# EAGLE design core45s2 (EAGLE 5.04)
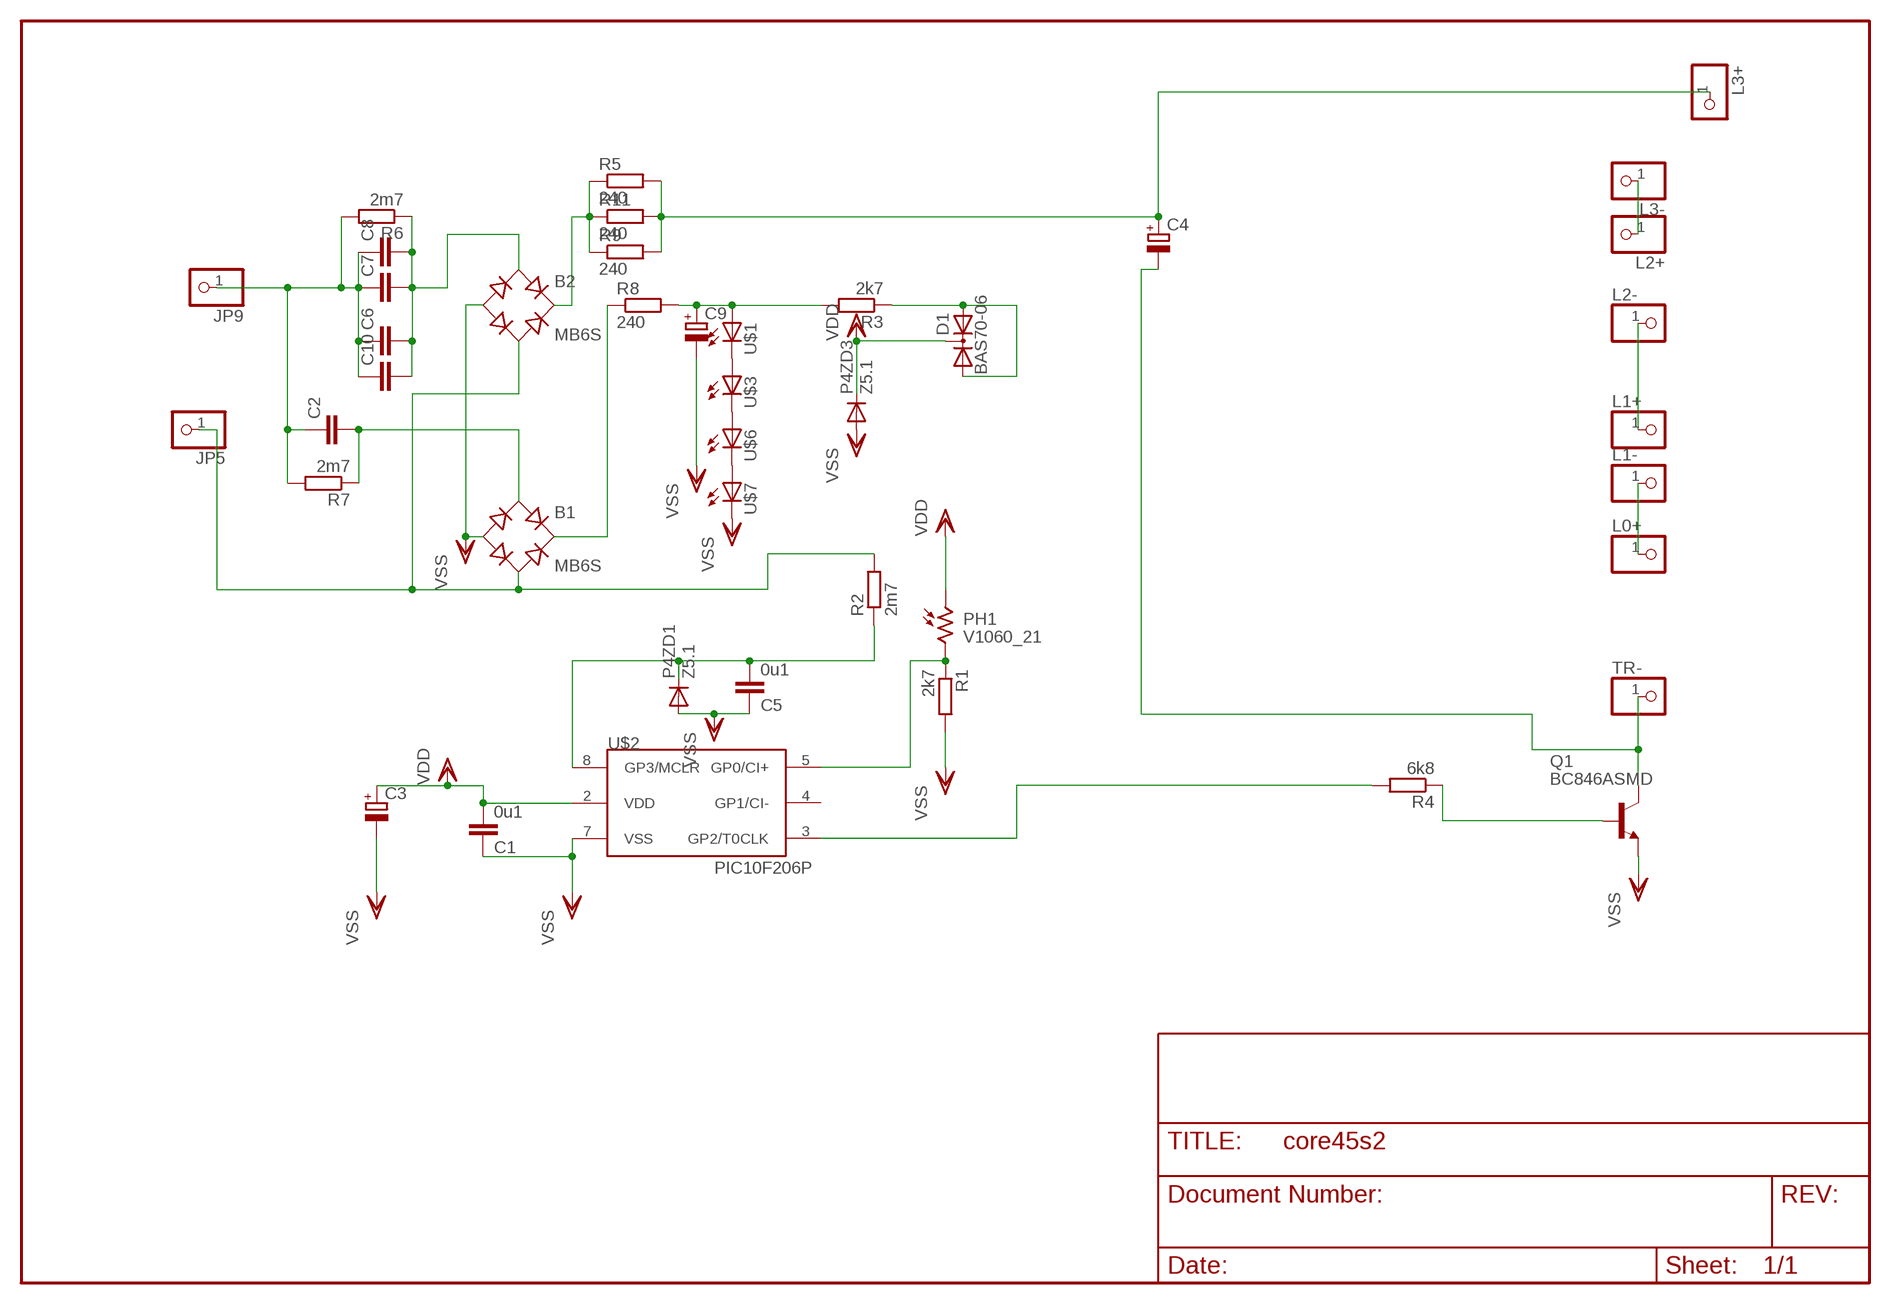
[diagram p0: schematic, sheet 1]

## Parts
B1  MB6S  [SOIC-4]
B2  MB6S  [SOIC-4]
C1  0u1  C-EUC1206  [C1206]
C2  C-EU102-043X133  [C102-043X133]
C3  CPOL-EU5-13  [2,5-5-FLAT]
C4  CPOL-EUTT5D11L  [TT5D11L]
C5  0u1  C-EUC1206  [C1206]
C6  C-EU150-064X183  [C150-064X183]
C7  C-EU150-054X183  [C150-054X183]
C8  C-EU150-054X183  [C150-054X183]
C9  CPOL-EUTT5D11L  [TT5D11L]
C10  C-EU150-064X183  [C150-064X183]
D1  BAS70-06  [SOT23]
JP5  PINHD-1X1  [1X01]
JP9  PINHD-1X1  [1X01]
L0+  PINHD-1X1  [1X01]
L1+  PINHD-1X1  [1X01]
L1-  PINHD-1X1  [1X01]
L2+  PINHD-1X1  [1X01]
L2-  PINHD-1X1  [1X01]
L3+  PINHD-1X1  [1X01]
L3-  PINHD-1X1  [1X01]
P4ZD1  Z5.1  DIODE-MINIMELF  [MINIMELF]
P4ZD3  Z5.1  DIODE-MINIMELF  [MINIMELF]
PH1  V1060_21  [TO-5_V10]
Q1  BC846ASMD  [SOT23]
R1  2k7  R-EU_R0805  [R0805]
R2  2m7  R-EU_R1206  [R1206]
R3  2k7  R-EU_R0805  [R0805]
R4  6k8  R-EU_R0805  [R0805]
R5  240  R-EU_0204/2V  [0204V]
R6  2m7  R-EU_R1206  [R1206]
R7  2m7  R-EU_R1206  [R1206]
R8  240  R-EU_0204/5  [0204/5]
R9  240  R-EU_0204/5  [0204/5]
R11  240  R-EU_0204/5  [0204/5]
TR-  PINHD-1X1  [1X01]
U$1  LED5MM  [LED5MM]
U$2  PIC10F206P  [DIL8]
U$3  LED5MM  [LED5MM]
U$6  LED5MM  [LED5MM]
U$7  LED5MM  [LED5MM]

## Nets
AC1: B1.~2(AC2) B2.~2(AC2) JP5.1 R2.2
AC2: C2.1 C6.1 C7.1 C8.1 C10.1 JP9.1 R6.2 R7.2
D+: C4.+ L3+.1 R5.2 R9.2 R11.2
LED-: C4.- Q1.3(C) TR-.1
N$1: C5.2 P4ZD1.C R2.1 U$2.8(GP3/MCLR)
N$2: B1.+ R8.1
N$3: L0+.1 L1-.1
N$4: C9.+ R3.2 R8.2 U$1.A
N$5: D1.1(A1) D1.2(A2) R3.1
N$6: L1+.1 L2-.1
N$7: U$1.K(C) U$3.A
N$8: B1.~1(AC1) C2.2 R7.1
N$9: B2.~1(AC1) C6.2 C7.2 C8.2 C10.2 R6.1
N$10: U$3.K(C) U$6.A
N$11: B2.+ R5.1 R9.1 R11.1
N$12: Q1.1(B) R4.1
N$13: L2+.1 L3-.1
N$15: R4.2 U$2.3(GP2/T0CLK)
N$16: U$6.K(C) U$7.A
N$17: PH1.2 R1.1 U$2.5(GP0/CI+)
VDD: C1.2 C3.+ D1.3(C) P4ZD3.C PH1.1 U$2.2(VDD)
VSS: B1.- B2.- C1.1 C3.- C5.1 C9.- P4ZD1.A P4ZD3.A Q1.2(E) R1.2 U$2.7(VSS) U$7.K(C)
Unconnected: U$2.4(GP1/CI-)

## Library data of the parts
B1 B2 = rectifier:MB*S: Bridge Rectifier Source: http://www.fairchildsemi.com/ds/MB/MB6S.pdf
C1 C5 = rcl:C-EU: CAPACITOR, European symbol
C2 C6-C8 C10 = rcl-2:C-EU: CAPACITOR, European symbol
C3 C4 C9 = rcl-2:CPOL-EU: POLARIZED CAPACITOR, European symbol
D1 = diode:BAS70-06: Silicon Schottky Diodes General-purpose diode for high-speed switching
JP5 JP9 L0+ L1+ L1- L2+ L2- L3+ L3- TR- = pinhead(2):PINHD-1X1: PIN HEADER
P4ZD1 P4ZD3 = diode:DIODE-: DIODE
PH1 = photo-elements:?1060*: Sensor Street Light control
Q1 = transistor-npn:BC846*: NPN Transistor
R1-R9 R11 = rcl-2:R-EU_: RESISTOR, European symbol
U$1 U$3 U$6 U$7 = led(3):LED: LED
U$2 = microchip-3:PIC10F2*: uPC nW 0,25/0,5k Program Flash memory Comparator

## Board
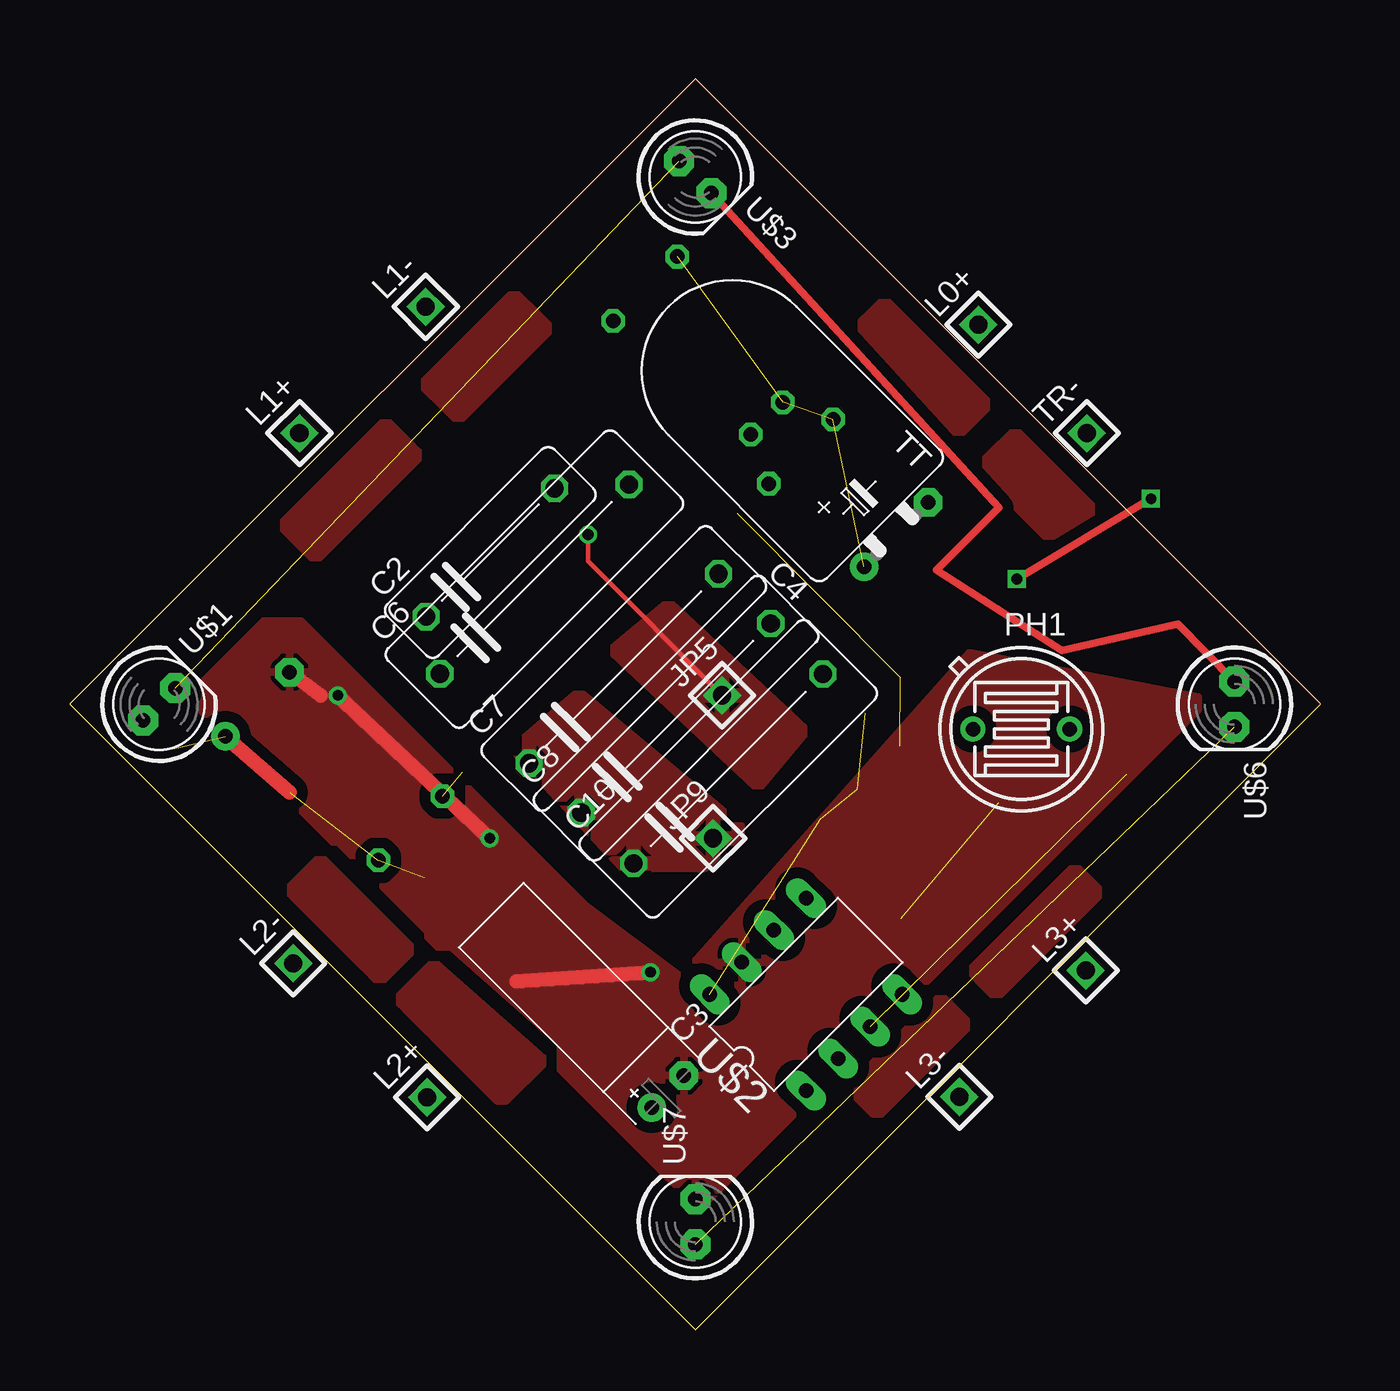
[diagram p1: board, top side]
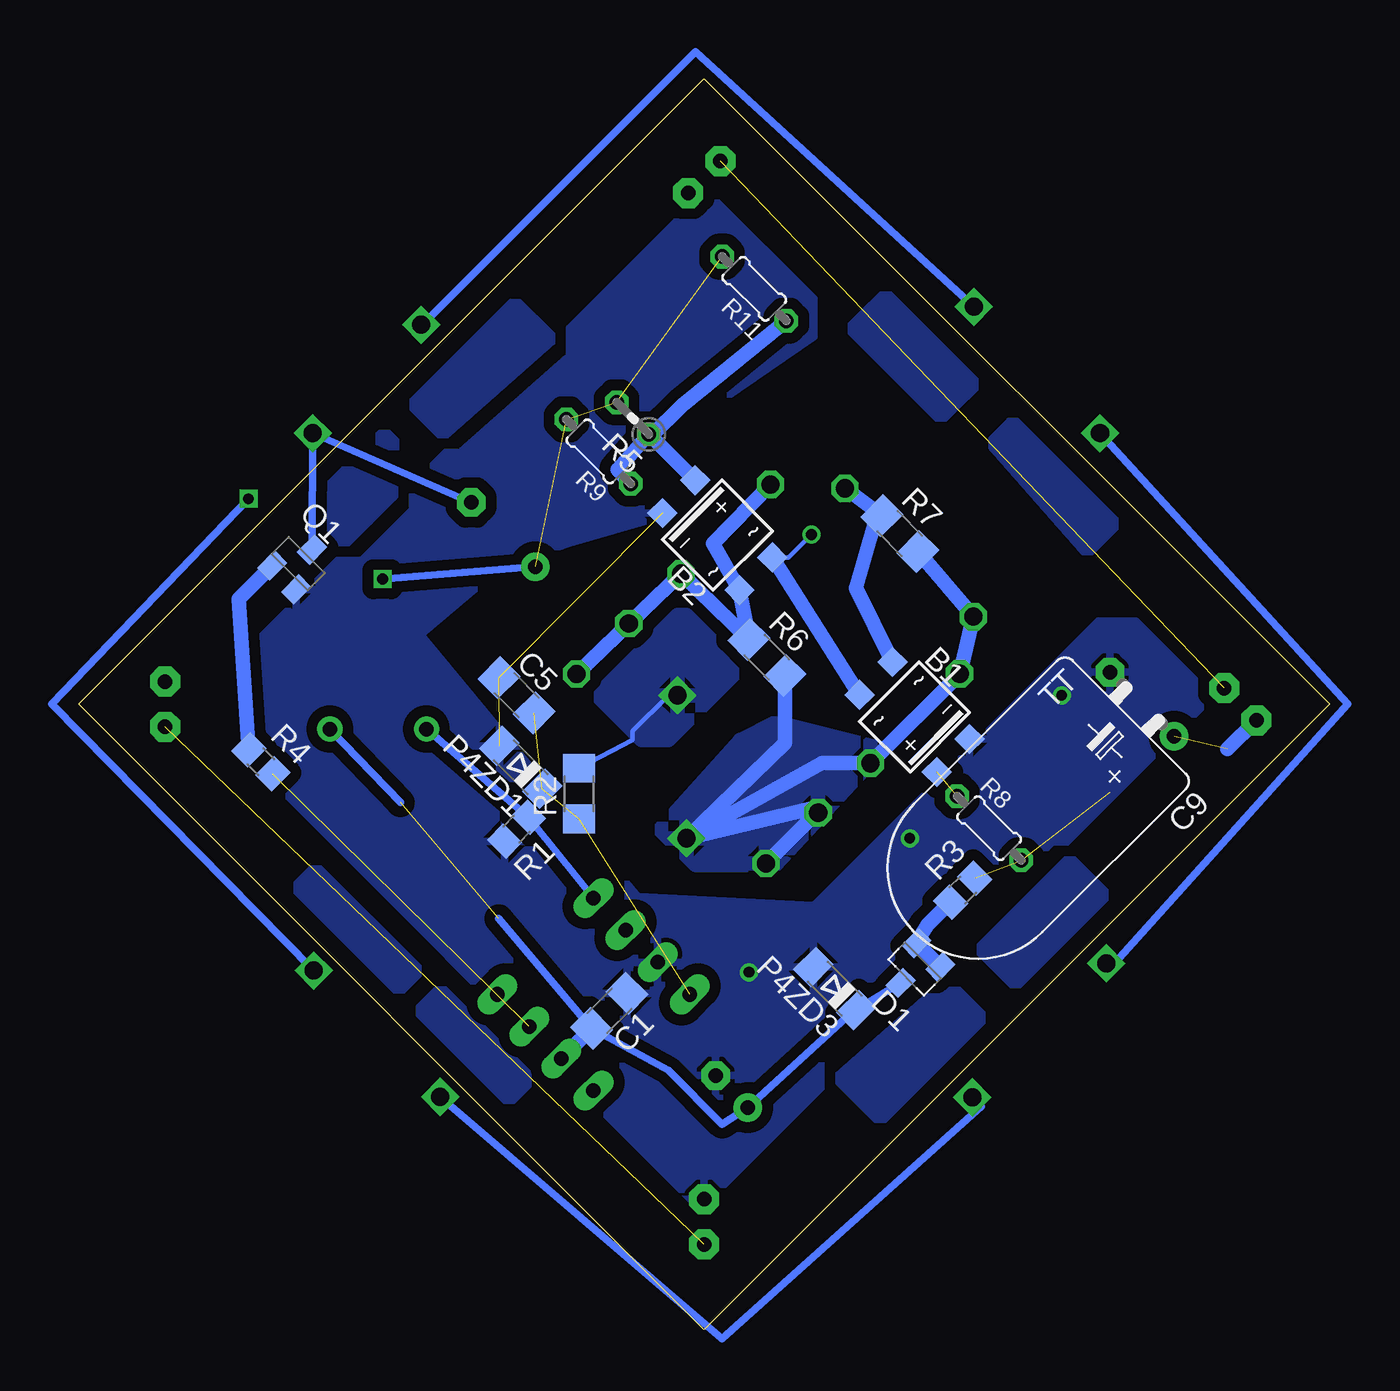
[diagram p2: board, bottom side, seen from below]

Size 70 x 70 mm. Coordinates in mm from the lower left corner, seen from the top.
Outline: 35,0 70,35 35,70 0,35 35,0
Copper layers (1*16): Top 0.035mm / dielectric 1.5mm / Bottom 0.035mm
Design rules "default": minimum track width 10mil, minimum drill 24mil, track to track 8mil, track to pad 8mil, pad to pad 8mil, via to via 8mil, smd to smd 8mil, copper to edge 40mil, drill to drill 8mil, minimum pad ring 10mil, minimum via ring 8mil, stop-mask expansion 4mil, vias tented up to drill 0mil, thermal gap 10mil

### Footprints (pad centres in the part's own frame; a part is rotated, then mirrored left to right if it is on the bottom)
SOIC-4 = smd 1.2 x 1.2: + 1.3,3.05; - -1.3,3.05; ~1 -1.3,-3.05; ~2 1.3,-3.05
C1206 = smd 1.6 x 1.8: 1 -1.4,0; 2 1.4,0
C102-043X133 = drill 1.016 octagon: 1 -5.08,0; 2 5.08,0
2,5-5-FLAT = drill 0.813 pad 1.6 round: + -1.27,0 | drill 0.813 pad 1.6 octagon: - 1.27,0
TT5D11L = drill 0.813 pad 1.6 round: + -2.54,0 | drill 0.813 pad 1.6 octagon: - 2.54,0
C150-064X183 = drill 1.016 octagon: 1 -7.493,0; 2 7.493,0
C150-054X183 = drill 1.016 octagon: 1 -7.493,0; 2 7.493,0
SOT23 = smd 1 x 1.4: 1 -0.95,-1.1; 2 0.95,-1.1; 3 0,1.1
1X01 = drill 1.016 square: 1 0,0
MINIMELF = smd 1.4 x 1.8: A 1.7,0; C -1.7,0
TO-5_V10 = drill 0.8 pad 1.4 round: 1 -2.7,0; 2 2.7,0
R0805 = smd 1.3 x 1.5: 1 -0.95,0; 2 0.95,0
R1206 = smd 1.6 x 1.803: 1 -1.422,0; 2 1.422,0
0204V = drill 0.813 octagon: 1 -1.27,0; 2 1.27,0
0204/5 = drill 0.813 octagon: 1 -2.54,0; 2 2.54,0
LED5MM = drill 0.813 pad 1.676 octagon: A -1.27,0; K 1.27,0
DIL8 = drill 0.813 long: 1 -3.81,-3.81; 2 -1.27,-3.81; 3 1.27,-3.81; 4 3.81,-3.81; 5 3.81,3.81; 6 1.27,3.81; 7 -1.27,3.81; 8 -3.81,3.81

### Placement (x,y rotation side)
B1  23.22,34.29 225 bottom
B2  34.27,44.46 45 bottom
C1  40.31,17.84 225 bottom
C2  23.53,43.49 45 top
C3  33.46,13.32 45 top
C4  46.24,44.49 45 top
C5  45.5,35.5 315 bottom
C6  26,42 45 top
C7  31,37 45 top
C8  33.92,34.22 45 top
C9  10.5,35 135 bottom
C10  36.84,31.39 45 top
D1  23.23,20.19 135 bottom
JP5  36.5,35.5 45 top
JP9  36,27.5 45 top
L0+  50.84,56.24 45 top
L1+  12.85,50.17 45 top
L1-  19.92,57.24 45 top
L2+  20,13 45 top
L2-  12.5,20.5 45 top
L3+  56.85,20.1 45 top
L3-  49.78,13.03 45 top
P4ZD1  45.26,31.47 135 bottom
P4ZD3  27.7,19.09 135 bottom
PH1  53.25,33.61 180 top
Q1  57.73,42.87 315 bottom
R1  45.5,28 225 bottom
R2  42,30 90 bottom
R3  20.54,24.6 45 bottom
R4  59.81,31.78 315 bottom
R5  39,51 135 bottom
R6  31.5,37.62 315 bottom
R7  24.06,44.55 315 bottom
R8  19.06,28.06 315 bottom
R9  40.92,49.14 135 bottom
R11  32.2,58.25 135 bottom
TR-  56.91,50.17 45 top
U$1  5,35 45 top
U$2  41.2,18.76 45 top
U$3  35,64.5 315 top
U$6  65.17,35 270 top
U$7  35,6.04 90 top

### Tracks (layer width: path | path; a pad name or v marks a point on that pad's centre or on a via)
AC1  (via drill 0.6)
  Top 0.254: JP5.1 29,43 v29,44.5
  Bottom 0.254: v29,44.5 30.28,43.22 B2.~2 | R2.2 39,33 39,33.5 37,35.5 JP5.1
  Bottom 0.813: B1.~2 B2.~2
  pour Bottom (isolate 0.61): 33,37 37,33 38.5,33 41,35.5 36.5,40 36,40
  pour Top (isolate 0.61): 30.5,38 38.5,30.5 41,33.5 33.5,40.5
AC2
  Bottom 0.813: JP9.1 28.41,31.7 C7.1 C6.1 C2.1 R7.2 | JP9.1 28.89,29.19 C8.1 28.71,28.93 C10.1 | JP9.1 30.49,32.83 R6.2
  pour Bottom (isolate 0.813, rank 2): 25,32.5 31,34 33,33 37.5,28 35.5,26 31,26
  pour Top (isolate 0.813, rank 2): 25,32.5 28.5,35.5 37.5,28 35.5,26 31,26
D+  (via drill 0.6)  (3 unrouted)
  Top 0.406: v60.5,46.5 v53,42
  Bottom 0.406: L3+.1 71.5,35 v60.5,46.5 | v53,42 C4.+
  pour Bottom (isolate 0.61, rank 2): 49.61,50.14 51.73,52.26 46.07,57.92 45.72,57.57 43.6,55.45
  pour Top (isolate 0.61, rank 2): 49.61,50.14 51.73,52.26 46.07,57.92 45.72,57.57 43.6,55.45
  pour Bottom (isolate 0.61, rank 2): 18.86,49.61 16.74,51.73 11.08,46.07 11.43,45.72 13.55,43.6
  pour Top (isolate 0.61, rank 2): 58.36,23.61 56.24,25.73 50.58,20.07 50.93,19.72 53.05,17.6
  pour Top (isolate 0.61, rank 2): 20.39,20.36 18.27,18.24 23.93,12.58 24.28,12.93 26.4,15.05
  pour Top (isolate 0.61, rank 2): 11.64,45.39 13.76,43.27 19.42,48.93 19.07,49.28 16.95,51.4
  pour Bottom (isolate 0.61, rank 2): 58.86,23.61 56.74,25.73 51.08,20.07 51.43,19.72 53.55,17.6
  pour Bottom (isolate 0.61, rank 2): 21.39,19.36 19.27,17.24 24.93,11.58 25.28,11.93 27.4,14.05
D-
  pour Bottom (isolate 0.61): 58.45,45.75 55.97,43.28 51.02,48.23 53.5,50.7
  pour Top (isolate 0.61): 58.45,45.75 55.97,43.28 51.02,48.23 53.5,50.7
  pour Top (isolate 0.61): 48.75,18.45 51.22,15.97 46.27,11.02 43.8,13.5
  pour Top (isolate 0.61): 11.55,23.75 14.03,26.22 18.98,21.27 16.5,18.8
  pour Top (isolate 0.61): 21.75,51.05 19.28,53.53 24.23,58.48 26.7,56
  pour Bottom (isolate 0.61): 49.75,18.95 52.22,16.47 47.27,11.52 44.8,14
  pour Bottom (isolate 0.61): 12.05,23.75 14.53,26.22 19.48,21.27 17,18.8
  pour Bottom (isolate 0.61): 21.75,51.05 19.28,53.53 24.23,58.48 26.7,56
LED-
  Bottom 0.406: C4.- TR-.1 Q1.3
N$1  (3 unrouted)
N$2  (1 unrouted)
N$3
  Bottom 0.406: L0+.1 50.5,56.5 35.5,71.5 L1-.1
N$4  (3 unrouted)
  Top 0.813: 12.29,30.06 C9.+
  Bottom 0.813: U$1.A 5.72,32.48
N$5
  Bottom 0.813: R3.1 22.5,22.64 D1.2 D1.1
N$6
  Bottom 0.406: L1+.1 -1,35 12.5,20 L2-.1
N$7  (1 unrouted)
N$8
  Bottom 0.813: C2.2 R7.1 25.5,45 26.5,41.5 B1.~1
N$9
  Bottom 0.813: C6.2 34.5,44 B2.~1 R6.1 C7.2 C8.2 C10.2
N$10
  Top 0.406: U$6.A 62,39.5 55.5,38 48.5,42.5 52,46 U$3.K
N$11
  Bottom 0.813: B2.+ 37.97,49.99 | 37.97,49.99 R5.1 39.85,48.14 R9.1 | 37.97,49.99 36.22,51.74 R11.1
N$12
  Bottom 0.813: Q1.1 61.05,40.89 R4.1
N$13
  Bottom 0.406: L2+.1 19.5,12.5 34,-0.5 L3-.1
N$15  (1 unrouted)
N$16  (1 unrouted)
N$17
  Bottom 0.406: U$2.5 R1.1 PH1.2
VDD  (1 unrouted)
  Bottom 0.406: 46.5,23 C1.2 37,14.5 34,11.5 C3.+ 27,17.5 P4ZD3.C D1.3 | 52,29.5 PH1.1
  Bottom 0.813: C1.2 U$2.2
VSS  (via drill 0.6)  (2 unrouted)
  Top 0.813: C9.- 14.04,35.5 | v15,35.5 v23.5,27.5 | 25,19.5 v32.5,20
  pour Bottom (isolate 0.61, rank 5): 6.59,35.41 10.84,39.66 12.96,39.66 28.87,23.75 38.7,24.25 50.84,38.89 46.34,42.72 42.54,44.02 37.29,45.52 39.73,48.08 28.87,55.57 28.87,57.69 34.53,63.34 35.23,63.34 63.16,35.41 63.16,34.71 35.59,7.13 34.88,7.13
  pour Top (isolate 0.61, rank 5): 6.59,35.41 10.84,39.66 12.96,39.66 28.87,23.75 34.2,19.75 50.34,37.89 63.16,35.41 63.16,34.71 35.59,7.13 34.88,7.13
